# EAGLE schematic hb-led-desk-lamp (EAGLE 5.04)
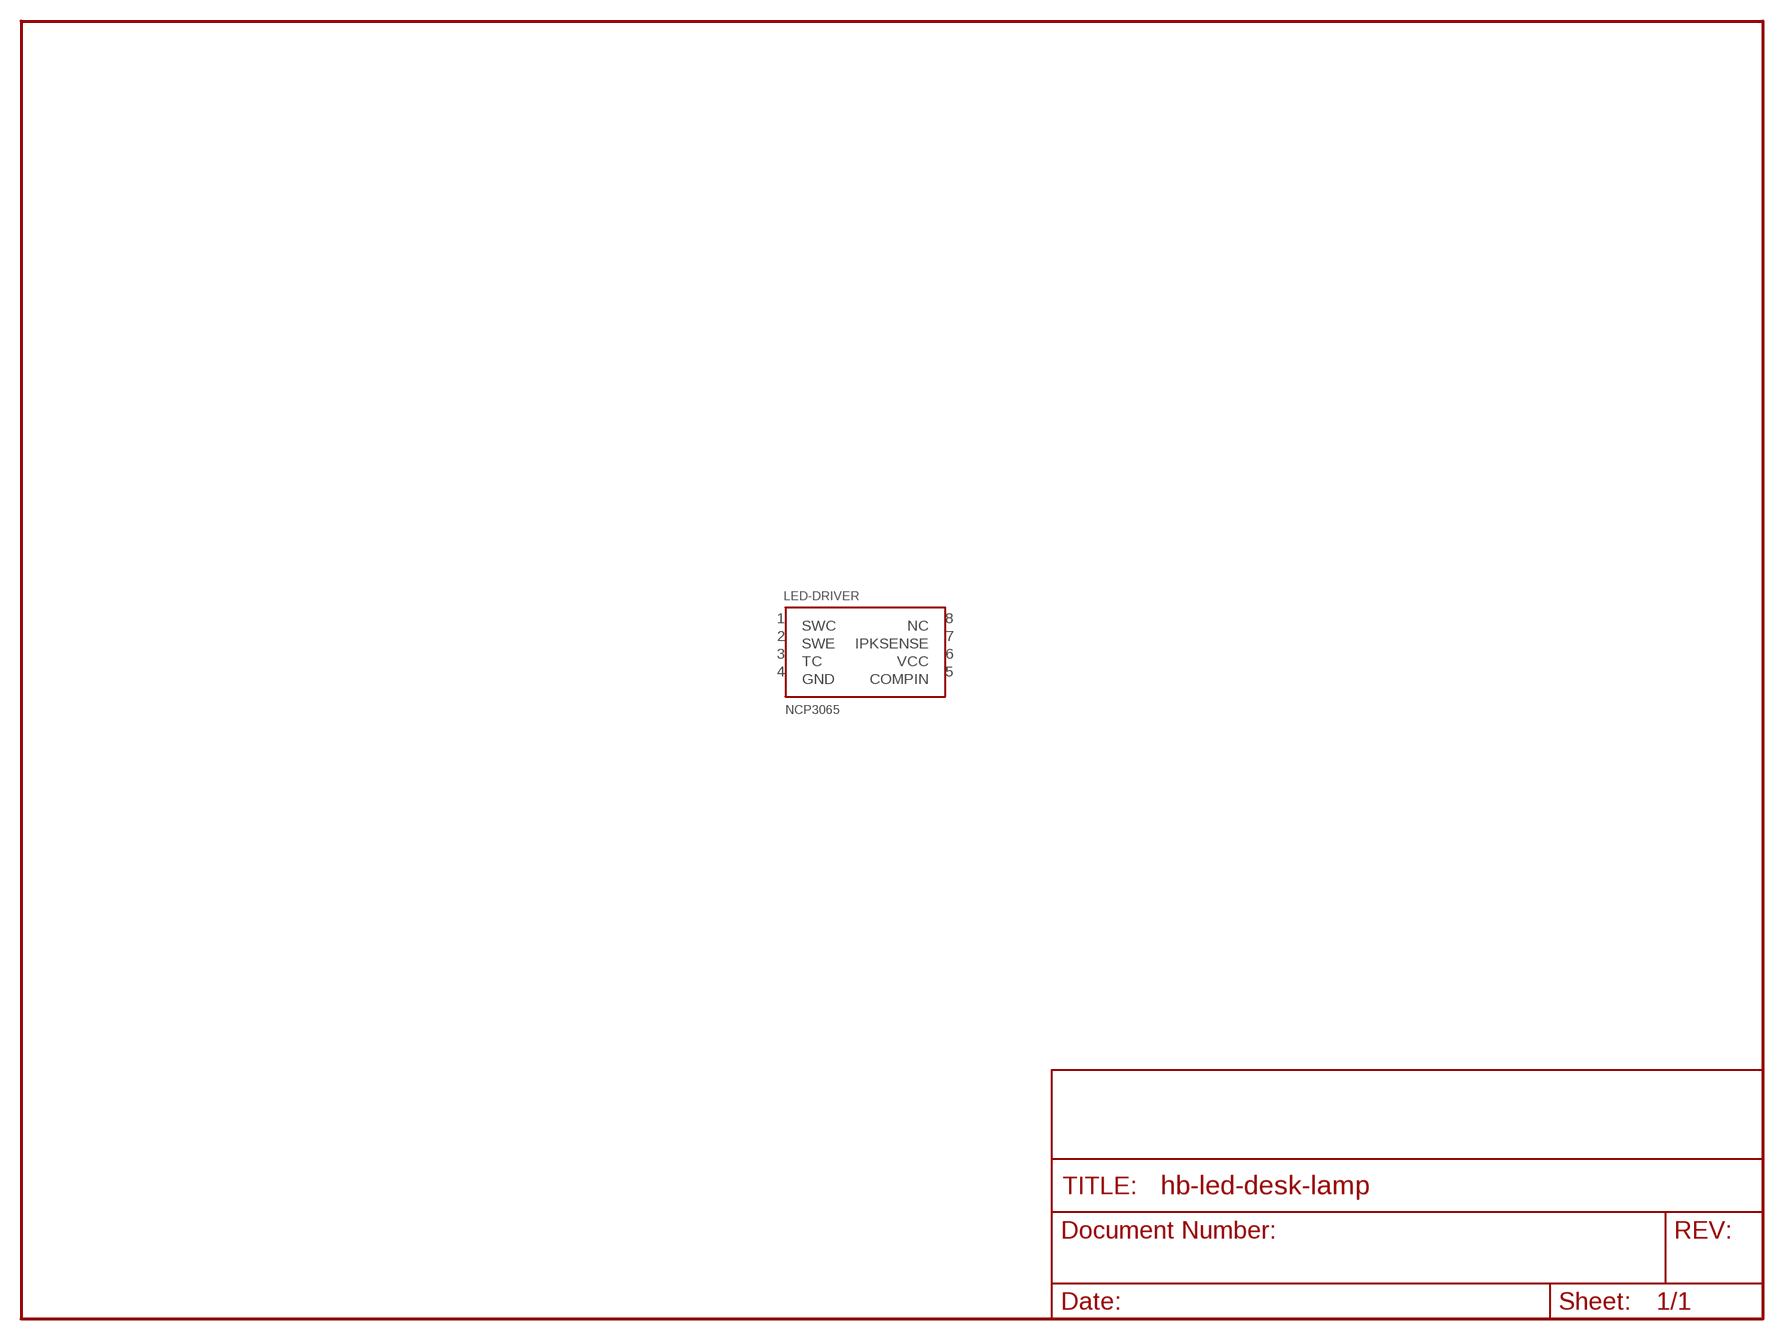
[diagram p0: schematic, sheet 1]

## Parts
LED-DRIVER  NCP3065  [DIL8-3]
Unconnected: LED-DRIVER.1(SWC) LED-DRIVER.2(SWE) LED-DRIVER.3(TC) LED-DRIVER.4(GND) LED-DRIVER.5(COMPIN) LED-DRIVER.6(VCC) LED-DRIVER.7(IPKSENSE) LED-DRIVER.8(NC)

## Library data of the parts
LED-DRIVER = trl:NCP3065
